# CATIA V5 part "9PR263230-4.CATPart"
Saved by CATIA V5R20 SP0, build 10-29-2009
Part number: 9PR263230-4
Revision: ANY
Definition: UNKNOWN
Nomenclature: 9PR263230-4
Source: Unknown
Bounding box of the stored display mesh (mm): x -2.5 to 2.5, y -2.5 to 2.5, z -2.5 to 2.5
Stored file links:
  C:\Users\Utente\Desktop\IO LAVORO\3D X SITO CF\CUMSA\3D files PR.233230\PR 263230\9PR263230-4.CATPart
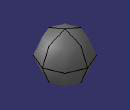
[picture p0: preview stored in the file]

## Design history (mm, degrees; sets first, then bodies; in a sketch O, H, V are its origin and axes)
Body1 "Revolución1" (main body)
  Solid1: solid without history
